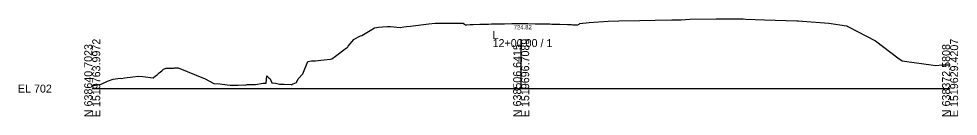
# Model space of a CAD drawing. Extents: x -26 to 3903, y -10 to 9531.
# Drawn here: x -25.7 to 302.8, y 1990.3 to 2024.5 of the extents above; entities that cross this region are included whole.
import ezdxf

# ---------------------------------------------------------------- set-up
doc = ezdxf.new("R2010")
doc.units = 0
for name, color, linetype in [('Default', 7, 'Continuous'), ('Exist Cross Section Cell', 7, 'Continuous'), ('Exist XS Center Line Elevation Label', 7, 'Continuous'), ('Exist XS Ground Line', 7, 'Continuous')]:
    doc.layers.add(name, color=color, linetype=linetype)

msp = doc.modelspace()

# ---------------------------------------------------------------- linework, layer by layer
at = {"layer": 'Exist Cross Section Cell'}
for p, q in [((150, 2000), (150, 2017.35)), ((0, 2000), (150, 2000)), ((150, 2000), (300, 2000))]:
    msp.add_line(p, q, dxfattribs=at)
at = {"layer": 'Exist XS Ground Line'}
msp.add_lwpolyline([(0, 2000.78), (0.12, 2000.86), (0.55, 2001.03), (3.17, 2001.58), (5.32, 2002.55), (7.37, 2003.25), (9.8, 2003.61), (10.2, 2003.52), (11.33, 2003.8), (14.21, 2004.17), (16.14, 2004.32), (17.64, 2004.19), (21.34, 2003.77), (22.12, 2004.44), (22.71, 2004.84), (23.41, 2005.48), (24.32, 2006.28), (24.97, 2006.81), (25.83, 2007.14), (26.41, 2007.15), (28.47, 2007.22), (28.8, 2007.24), (29.07, 2007.25), (29.25, 2007.25), (29.61, 2007.27), (30.01, 2007.28), (30.06, 2007.28), (39.44, 2003.46), (42.46, 2001.84), (44.58, 2001.68), (46.35, 2001.41), (47.23, 2001.34), (48.23, 2001.21), (50.93, 2001.25), (51.07, 2001.25), (52.99, 2001.35), (53.44, 2001.17), (54.18, 2001.41), (57.14, 2001.43), (59.73, 2001.91), (60.38, 2001.95), (60.87, 2001.86), (61, 2004.44), (61.66, 2003.86), (62.19, 2003.46), (62.75, 2002.05), (64.04, 2001.89), (65.54, 2001.59), (67.06, 2001.56), (67.07, 2001.55), (67.08, 2001.55), (69.53, 2001.48), (69.72, 2001.47), (69.8, 2001.4), (69.89, 2001.41), (70.2, 2001.63), (70.27, 2001.69), (71.38, 2002.19), (71.97, 2003.39), (73.67, 2005.21), (75.38, 2009.49), (76.65, 2009.72), (78.06, 2009.7), (79.89, 2009.92), (81.06, 2010.07), (83.37, 2010.36), (83.77, 2010.46), (85.1, 2011.33), (88.97, 2014.28), (89.23, 2014.46), (89.54, 2014.82), (91.46, 2017.26), (91.5, 2017.28), (91.61, 2017.34), (93.79, 2018.47), (94.25, 2018.65), (97.14, 2020.37), (98.7, 2021.28), (100.14, 2021.5), (101.53, 2021.61), (103.19, 2021.76), (104.25, 2021.72), (107.65, 2021.46), (108.92, 2021.62), (109.89, 2021.72), (111.29, 2021.85), (117.73, 2022.68), (119.91, 2022.95), (120.65, 2022.95), (122.22, 2022.94), (129.77, 2022.88), (130.14, 2022.57), (130.38, 2022.37), (131.03, 2022.4), (132.14, 2022.45), (132.96, 2022.46), (133.16, 2022.47), (135.54, 2022.53), (136.55, 2022.55), (138.34, 2022.6), (138.52, 2022.61), (139.58, 2022.65), (140.39, 2022.66), (141.14, 2022.67), (143.73, 2022.74), (143.92, 2022.74), (144.12, 2022.75), (146.7, 2022.79), (149.34, 2022.81), (149.5, 2022.81), (149.69, 2022.82), (149.87, 2022.83), (149.9, 2022.83), (150.06, 2022.83), (152.32, 2022.79), (154.95, 2022.76), (155.11, 2022.75), (155.27, 2022.75), (157.9, 2022.7), (158.87, 2022.68), (159.99, 2022.67), (160.7, 2022.63), (160.82, 2022.63), (163.49, 2022.55), (166.21, 2022.46), (166.29, 2022.46), (166.32, 2022.46), (167.2, 2022.43), (167.64, 2022.42), (168.08, 2022.4), (169.27, 2022.37), (169.87, 2022.35), (170.25, 2022.64), (170.51, 2022.84), (173.74, 2023.13), (180.39, 2023.68), (184.2, 2023.8), (191.51, 2023.91), (196.86, 2023.96), (202.67, 2024.07), (203.64, 2024.08), (205.92, 2024.1), (208.98, 2024.28), (218.16, 2024.44), (225.5, 2024.49), (227.68, 2024.4), (228.57, 2024.39), (235.15, 2024.09), (246.46, 2023.81), (246.82, 2023.8), (248.41, 2023.64), (257.58, 2022.95), (263.77, 2022.03), (263.81, 2022.02), (263.87, 2022.02), (264.29, 2021.8), (273.95, 2016.74), (281.76, 2010.83), (283.23, 2009.76), (284.89, 2009.52), (293.38, 2008.28), (294.88, 2008.13), (297.29, 2008.36), (298.52, 2008.32), (300, 2008.36)], dxfattribs=at)

# ---------------------------------------------------------------- texts
at = {"layer": 'Default'}
msp.add_text('-', height=0.0001, dxfattribs=at).set_placement((0, 2000))
at = {"layer": 'Exist Cross Section Cell'}
for s, p in [('E 1519763.9972', (2.8, 1990)), ('E 1519696.7089', (152.8, 1990)), ('E 1519629.4207', (302.8, 1990)), ('N 638640.7023', (0, 1990)), ('N 638506.6415', (150, 1990)), ('N 638372.5808', (300, 1990))]:
    msp.add_text(s, height=2.8, rotation=90, dxfattribs=at).set_placement(p)
for s, p in [('12+00.00 / 1', (140, 2014.55)), ('L', (140, 2017.35)), ('EL 702', (-26, 1998.6))]:
    msp.add_text(s, height=2.8, dxfattribs=at).set_placement(p)
at = {"layer": 'Exist XS Center Line Elevation Label'}
msp.add_text('724.82', height=1.5, rotation=0.8401, dxfattribs=at).set_placement((147.39, 2020.72))

doc.saveas('drawing.dxf')
